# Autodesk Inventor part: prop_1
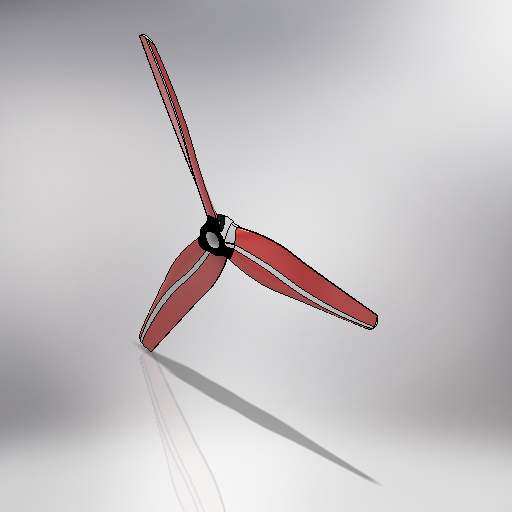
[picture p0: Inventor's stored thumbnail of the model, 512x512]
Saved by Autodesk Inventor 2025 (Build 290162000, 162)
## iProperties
Created: 2022-03
Part Number: prop_1
Material: Generic
Document SubType Name: Modeling
Designer: casper
Density: 1 g/cm^3
Appearance: Default
Author: casper
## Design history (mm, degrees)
sketch "Sketch1"
  geometry: C1 r 8 at (0, 0); C2 r 4.5 at (0, 0); C3 r 101.6 at (0, 0); 1 further point
  constraints: 3 centre point, 3 coincident
  dimensions: "d0" = 16 diameter of C1; "d1" = 9 diameter of C2; "d76" = 203.2 diameter of C3
extrude "Extrusion1" new body sketch "Sketch1" stored distance "d2" = 9; taper "d3" = 0 deg
workplane "Work Plane1"
workplane "Work Plane2"
workplane "Work Plane3"
workplane "Work Plane4"
loft "Loft3" dims "d38" = 0, "d39" = 90 deg, "d40" = 0, "d41" = 90 deg, "d42" = 0, "d43" = 90 deg, "d44" = 0, "d45" = 90 deg
sketch "Sketch7"
  geometry: L1 (101.6, -1.292)-(101.6, 4.5) reference; L2 (101.6, -2.575)-(101.6, -4.5) reference; L3 (101.6, -1.292)-(101.6, -2.575) reference; A1 r 7 centre (94.6, 1.606) between (95.508, -5.335) and (101.6, 1.606); 2 further points
  constraints: 2 point on circle, 1 centre point, 1 point on line, 1 tangent, 3 other
  dimensions: "d46" = 7 radius of A1
extrude "Extrusion2" cut sketch "Sketch7" extent not by distance; stored distance "d47" = 0; taper "d48" = 0 deg
pattern_circular "Circular Pattern1" dims "d51" = 360 deg
sketch "Sketch9"
  geometry: C1 r 4.5 at (0, 0) reference; A1 r 8 centre (0, 0) between (-5.764, 5.548) and (-2.621, -7.558); A2 r 8 centre (0, 0) between (-5.764, 5.548) and (-2.628, -7.556) reference; 4 further points
  constraints: 1 centre point, 1 coincident, 1 point on circle
extrude "Extrusion3" join sketch "Sketch9" distance "d54" = 1; taper "d55" = 0 deg
fillet "Fillet3" dims "d56" = 4
fillet "Fillet4" dims "d75" = 5
feature "ʂ耀ʄ耀ʆ耀ʈ耀ʊ耀ʌ耀ʎ耀ʐ耀" dims "d0" = 16, "d1" = 9, "d2" = 9, "d3" = 0, "d4" = 5, "d7" = 12, "d8" = 0, "d9" = 2, "d10" = 16, "d12" = 33, "d13" = 19, "d14" = 40, "d15" = 0.5, "d16" = 1, "d17" = 101.6, "d18" = 30, "d19" = 9, "d20" = 7.5 deg, "d27" = 54, "d28" = 80, "d29" = 17, "d38" = 0, "d39" = 90 deg, "d40" = 0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
body "Solid1"
sketch "Sketch2"
  geometry: L1 (-6, 2.5)-(6, -4.5); L2 (-4.5, 4.5)-(4.5, 4.5) reference; L3 (-8, -4.5)-(8, -4.5) reference; L4 (8, 4.5)-(-8, 4.5) reference; L5 (-0.257, 2.623)-(1.351, 1.685); L6 (6, -4.5)-(6, -4); A1 r 16 centre (7.263, 11.45) between (-6, 2.5) and (6, -4.5); A2 r 5.5 centre (-3.028, -2.128) between (-0.257, 2.623) and (-6, 2.5); A3 r 10.5 centre (-3.939, -7.385) between (6, -4) and (1.351, 1.685); 2 further points
  constraints: 6 end point, 6 point on circle, 3 centre point, 2 midpoint, 2 tangent, 1 parallel, 1 perpendicular, 1 vertical alignment
  dimensions: "d7" = 12 horizontal distance of L1.start L1.end; "d8" = 0 distance from line of L3 L1.end; "d9" = 2 distance from line of L4 L1.start; "d10" = 16 radius of A1; "d57" = 5.5 radius of A2; "d58" = 3 distance between parallel lines of L1 L5; "d59" = 10.5 radius of A3; "d60" = 0.5 distance of L1.end L6.end
sketch "Sketch3"
  geometry: L1 (-9.5, 4)-(9.5, -5.5); L2 (-1.69, 2.111)-(9.5, -5); L3 (8, 4.5)-(-8, 4.5) reference; L4 (-8, -4.5)-(8, -4.5) reference; L5 (9.5, -5.5)-(9.5, -5); A1 r 16 centre (7.263, 11.45) between (-6, 2.5) and (6, -4.5) reference; A2 r 5.5 centre (-3.028, -2.128) between (-0.257, 2.623) and (-6, 2.5) reference; A3 r 40 centre (17.246, 33.743) between (-9.5, 4) and (9.5, -5.5); A4 r 12.439 centre (-8.362, -8.387) between (-1.69, 2.111) and (-9.5, 4); 7 further points
  constraints: 6 end point, 4 point on circle, 2 centre point, 2 midpoint, 2 vertical alignment, 1 coincident, 1 tangent, 1 vertical, 1 other
  dimensions: "d13" = 19 horizontal distance of L1.end L1.start; "d14" = 40 radius of A3; "d15" = 0.5 distance from line of L3 L1.start; "d16" = 1 distance from line of L4 L1.end; "d61" = 12.43949 radius of A4; "d62" = 5.87155 deg angle of L1 L2; "d63" = 0.5 distance of L1.end L2.end
sketch "Sketch4"
  geometry: L1 (-1.292, -0.541)-(4.5, -1.992); L2 (-4.5, -1.158)-(4.5, -2.342); L3 (-6.382, 0)-(6.314, 0) reference; L4 (4.5, -2.342)-(4.5, -1.992); A1 r 30 centre (3.871, 27.651) between (-4.5, -1.158) and (4.5, -2.342); A2 r 3.873 centre (-2.233, -4.298) between (-1.292, -0.541) and (-4.5, -1.158); 2 further points
  constraints: 6 end point, 4 point on circle, 2 centre point, 1 midpoint, 1 tangent, 1 vertical, 1 vertical alignment
  dimensions: "d18" = 30 radius of A1; "d19" = 9 horizontal distance of L2.end L2.start; "d20" = 7.5 deg angle of L2 L3; "d64" = 1.75 distance of point (0, 0) point (0, -1.75); "d65" = 0.35 distance of L2.end L1.end; "d66" = 6.5685 deg angle of L2 L1; "d67" = 3.87335 radius of A2
sketch "Sketch6"
  geometry: L1 (-9, 1.501)-(8, -4.301); L2 (-4.728, 1.725)-(8, -3.801); L3 (8, 4.5)-(-8, 4.5) reference; L4 (8, -4.301)-(8, -3.801); A1 r 80 centre (25.177, 73.833) between (-9, 1.501) and (8, -4.301); A2 r 4.8 centre (-6.639, -2.678) between (-4.728, 1.725) and (-9, 1.501); 2 further points
  constraints: 6 end point, 4 point on circle, 2 centre point, 1 midpoint, 1 tangent, 1 vertical
  dimensions: "d28" = 80 radius of A1; "d29" = 17 horizontal distance of L1.start L1.end; "d68" = 18.8444 deg angle of L1 L3; "d69" = 1.4 vertical distance of point (0, 0) point (-0.5, -1.4); "d70" = 0.5 horizontal distance of point (0, 0) point (-0.5, -1.4); "d71" = 4.62274 deg angle of L1 L2; "d72" = 4.8 radius of A2; "d73" = 0.5 distance of L1.end L2.end
